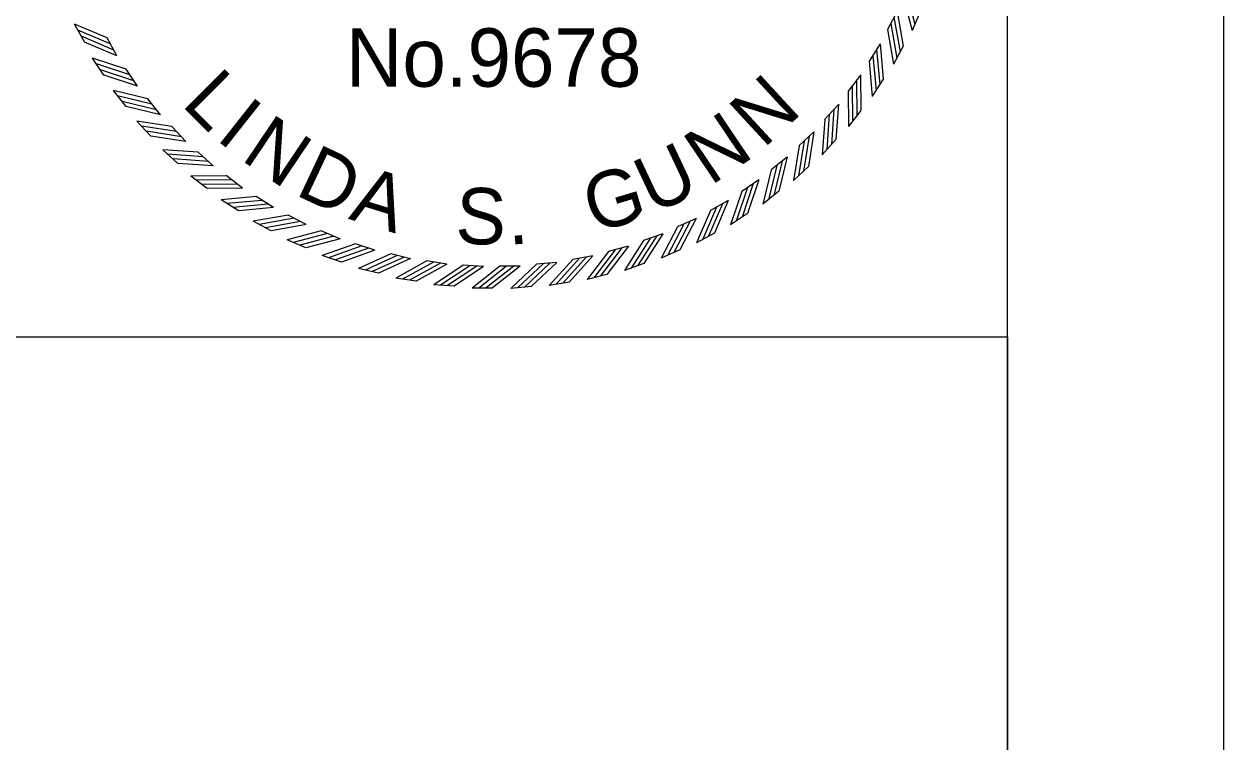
# Model space of a CAD drawing. Extents: x 0 to 1228740, y 0 to 152440.
# Drawn here: x 30.801 to 34, y 16.325 to 18.239 of the extents above; entities that cross this region are included whole.
import ezdxf

# ---------------------------------------------------------------- set-up
doc = ezdxf.new("R2010")
doc.units = 0
for name, color, linetype in [('R_Border', 7, 'Continuous'), ('R_No Plot', 7, 'Continuous'), ('STAMP', 7, 'Continuous')]:
    doc.layers.add(name, color=color, linetype=linetype)

msp = doc.modelspace()

# ---------------------------------------------------------------- linework, layer by layer
at = {"layer": 'R_Border'}
msp.add_line((33.4231, 0.5768), (33.4231, 21.4232), dxfattribs=at)
msp.add_lwpolyline([(33.9999, 22), (0, 22), (0, 0), (33.9999, 0)], close=True, dxfattribs=at)
at = {"layer": 'R_No Plot'}
for points in [[(30.6665, 20.1432), (30.6665, 17.4052), (33.4231, 17.4052)], [(33.4231, 17.4052), (33.4231, 10.8708)]]:
    msp.add_lwpolyline(points, dxfattribs=at)
at = {"layer": 'STAMP'}
for p, q in [((33.1283, 18.273), (33.1027, 18.2248)), ((33.1902, 18.2722), (33.1688, 18.2222)), ((30.9621, 18.1915), (30.9357, 18.2391)), ((31.0487, 18.1545), (31.0223, 18.2022)), ((33.083, 18.1863), (33.0536, 18.1403)), ((33.1447, 18.1803), (33.1192, 18.1323)), ((31.0141, 18.1031), (30.9839, 18.1484)), ((31.1035, 18.0734), (31.0732, 18.1188)), ((33.0308, 18.1035), (32.9977, 18.0601)), ((33.0917, 18.0925), (33.0624, 18.0467)), ((31.0733, 18.0193), (31.0395, 18.062)), ((31.1648, 17.9971), (31.1309, 18.0399)), ((32.9719, 18.0253), (32.9353, 17.9849)), ((31.1392, 17.9407), (31.102, 17.9804)), ((33.0317, 18.0093), (32.9987, 17.9661)), ((31.2322, 17.9262), (31.1949, 17.966)), ((32.9067, 17.9523), (32.8669, 17.915)), ((32.965, 17.9314), (32.9286, 17.8911)), ((31.2113, 17.8678), (31.1709, 17.9043)), ((31.3052, 17.861), (31.2648, 17.8976)), ((32.8357, 17.8849), (32.793, 17.851)), ((32.8922, 17.8593), (32.8525, 17.8221)), ((31.2892, 17.8012), (31.246, 17.8342)), ((31.3834, 17.8021), (31.34, 17.8352)), ((32.7595, 17.8236), (32.7141, 17.7933)), ((32.8136, 17.7934), (32.7709, 17.7596)), ((31.3724, 17.7411), (31.3266, 17.7705)), ((31.4661, 17.7499), (31.4202, 17.7793)), ((32.6784, 17.7688), (32.6306, 17.7424)), ((31.5529, 17.7046), (31.5047, 17.7301)), ((32.7298, 17.7342), (32.6845, 17.704)), ((31.4602, 17.6882), (31.4121, 17.7136)), ((32.593, 17.7208), (32.5433, 17.6985)), ((31.5521, 17.6427), (31.5021, 17.6641)), ((31.6432, 17.6667), (31.593, 17.6882)), ((32.504, 17.6801), (32.4526, 17.662)), ((32.6414, 17.6822), (32.5938, 17.6558)), ((31.7362, 17.6364), (31.6845, 17.6536)), ((32.4119, 17.6469), (32.3592, 17.633)), ((32.549, 17.6376), (32.4994, 17.6153)), ((31.6475, 17.6049), (31.5959, 17.6221)), ((31.8315, 17.6138), (31.7785, 17.6267)), ((31.9283, 17.5992), (31.8744, 17.6077)), ((32.0259, 17.5927), (31.9715, 17.5967)), ((32.2212, 17.6038), (32.1669, 17.5988)), ((32.3175, 17.6214), (32.2637, 17.6119)), ((32.4533, 17.6008), (32.402, 17.5827)), ((31.7456, 17.5751), (31.6928, 17.588)), ((32.1238, 17.5942), (32.0692, 17.5937)), ((32.3549, 17.572), (32.3023, 17.5582)), ((31.8459, 17.5536), (31.7922, 17.5621)), ((31.9476, 17.5404), (31.8934, 17.5444)), ((32.0501, 17.5356), (31.9957, 17.5351)), ((32.1526, 17.5393), (32.0984, 17.5343)), ((32.2544, 17.5515), (32.2008, 17.5421))]:
    msp.add_line(p, q, dxfattribs=at)
for points in [[(33.1448, 18.3132), (33.1688, 18.2222)], [(33.1521, 18.3298), (33.1761, 18.2388)], [(33.1282, 18.2731), (33.1447, 18.1804)], [(31.0223, 18.2022), (30.9357, 18.2391)], [(33.1114, 18.2408), (33.1279, 18.1481)], [(33.1199, 18.2577), (33.1364, 18.165)], [(31.0309, 18.1862), (30.9443, 18.2232)], [(31.0404, 18.1699), (30.9538, 18.2068)], [(33.1028, 18.2249), (33.1193, 18.1322)], [(31.0487, 18.1545), (30.9621, 18.1914)], [(33.0734, 18.1717), (33.0822, 18.0779)], [(33.083, 18.1863), (33.0917, 18.0926)], [(31.0732, 18.1187), (30.9839, 18.1484)], [(33.0537, 18.1404), (33.0624, 18.0466)], [(33.0636, 18.1555), (33.0723, 18.0618)], [(31.0831, 18.1036), (30.9938, 18.1332)], [(31.094, 18.0881), (31.0046, 18.1177)], [(31.1035, 18.0734), (31.0142, 18.1031)], [(33.02, 18.0898), (33.021, 17.9956)], [(33.0308, 18.1036), (33.0317, 18.0094)], [(31.1309, 18.0398), (31.0394, 18.062)], [(31.142, 18.0255), (31.0505, 18.0477)], [(32.9977, 18.0602), (32.9987, 17.966)], [(33.0089, 18.0745), (33.0098, 17.9803)], [(31.1541, 18.0109), (31.0626, 18.0331)], [(31.1649, 17.9971), (31.0734, 18.0193)], [(32.96, 18.0125), (32.9532, 17.9186)], [(32.9719, 18.0254), (32.9651, 17.9315)], [(31.1949, 17.9659), (31.1019, 17.9804)], [(32.9354, 17.9849), (32.9286, 17.891)], [(32.9477, 17.9982), (32.9408, 17.9043)], [(31.2072, 17.9526), (31.1142, 17.9671)], [(31.2204, 17.939), (31.1274, 17.9536)], [(32.9067, 17.9524), (32.8922, 17.8594)], [(31.2323, 17.9262), (31.1393, 17.9407)], [(32.867, 17.915), (32.8525, 17.822)], [(32.8803, 17.9273), (32.8658, 17.8343)], [(32.8938, 17.9405), (32.8793, 17.8475)], [(31.2648, 17.8975), (31.1709, 17.9043)], [(31.2781, 17.8852), (31.1842, 17.8921)], [(32.8358, 17.885), (32.8136, 17.7935)], [(31.2924, 17.8729), (31.1985, 17.8797)], [(31.3053, 17.861), (31.2114, 17.8678)], [(32.7931, 17.851), (32.7709, 17.7595)], [(32.8074, 17.8621), (32.7852, 17.7706)], [(32.8219, 17.8742), (32.7998, 17.7827)], [(31.3401, 17.8351), (31.2459, 17.8342)], [(31.3544, 17.824), (31.2602, 17.8231)], [(32.7595, 17.8237), (32.7298, 17.7343)], [(31.3696, 17.8129), (31.2755, 17.8119)], [(31.3835, 17.8021), (31.2893, 17.8012)], [(32.7142, 17.7933), (32.6845, 17.704)], [(32.7293, 17.8032), (32.6997, 17.7139)], [(32.7448, 17.8141), (32.7152, 17.7247)], [(31.4203, 17.7792), (31.3265, 17.7705)], [(31.4354, 17.7693), (31.3417, 17.7606)], [(31.4516, 17.7595), (31.3578, 17.7507)], [(32.663, 17.7605), (32.6261, 17.6739)], [(32.6784, 17.7688), (32.6415, 17.6823)], [(31.4662, 17.7499), (31.3725, 17.7411)], [(31.5048, 17.7301), (31.4121, 17.7136)], [(32.6307, 17.7424), (32.5938, 17.6558)], [(32.6467, 17.751), (32.6097, 17.6644)], [(31.5207, 17.7215), (31.428, 17.705)], [(31.5376, 17.713), (31.4449, 17.6965)], [(31.553, 17.7046), (31.4603, 17.6882)], [(32.5434, 17.6985), (32.4994, 17.6152)], [(32.56, 17.7058), (32.516, 17.6225)], [(32.577, 17.7139), (32.5331, 17.6306)], [(32.5931, 17.7209), (32.5491, 17.6377)], [(31.5931, 17.6881), (31.5021, 17.6641)], [(31.6097, 17.6808), (31.5187, 17.6568)], [(31.6272, 17.6738), (31.5362, 17.6497)], [(31.6433, 17.6667), (31.5522, 17.6427)], [(32.4527, 17.6619), (32.402, 17.5826)], [(32.4698, 17.6678), (32.4191, 17.5885)], [(32.4875, 17.6745), (32.4368, 17.5952)], [(32.5041, 17.6802), (32.4534, 17.6009)], [(31.6845, 17.6536), (31.5958, 17.6221)], [(31.7017, 17.6477), (31.613, 17.6162)], [(31.7197, 17.6421), (31.631, 17.6106)], [(31.7363, 17.6364), (31.6476, 17.6049)], [(32.3593, 17.633), (32.3022, 17.5581)], [(32.3769, 17.6375), (32.3198, 17.5626)], [(32.395, 17.6427), (32.338, 17.5678)], [(32.412, 17.647), (32.3549, 17.5721)], [(31.7785, 17.6267), (31.6927, 17.588)], [(31.7961, 17.6222), (31.7103, 17.5835)], [(31.8146, 17.6182), (31.7288, 17.5795)], [(31.8316, 17.6139), (31.7457, 17.5752)], [(31.8744, 17.6077), (31.7921, 17.562)], [(31.8923, 17.6047), (31.81, 17.559)], [(31.9111, 17.6022), (31.8287, 17.5565)], [(31.9283, 17.5993), (31.846, 17.5536)], [(31.9716, 17.5966), (31.8933, 17.5443)], [(31.9896, 17.5951), (31.9114, 17.5428)], [(32.1669, 17.5988), (32.0983, 17.5343)], [(32.185, 17.6003), (32.1164, 17.5358)], [(32.2038, 17.6024), (32.1352, 17.538)], [(32.2212, 17.6039), (32.1526, 17.5394)], [(32.2638, 17.6119), (32.2008, 17.542)], [(32.2817, 17.6149), (32.2186, 17.545)], [(32.3002, 17.6186), (32.2372, 17.5487)], [(32.3175, 17.6215), (32.2545, 17.5516)], [(32.0085, 17.5942), (31.9302, 17.5419)], [(32.026, 17.5927), (31.9477, 17.5404)], [(32.0693, 17.5937), (31.9956, 17.5351)], [(32.0874, 17.5937), (32.0137, 17.5351)], [(32.1063, 17.5943), (32.0326, 17.5357)], [(32.1238, 17.5943), (32.0501, 17.5357)]]:
    msp.add_lwpolyline(points, dxfattribs=at)

# ---------------------------------------------------------------- texts
msp.add_text('No.9678', height=0.15578, dxfattribs=at).set_placement((31.6592, 18.0722))
for s, rotation, p in [('L', 315.1295, (31.218, 18.0244)), ('N', 42.6817, (32.7717, 17.9056)), ('I', 321.696, (31.3094, 17.9334)), ('N', 326.0736, (31.3759, 17.8788)), ('N', 33.9264, (32.6309, 17.8069)), ('U', 25.1712, (32.4767, 17.7308)), ('D', 334.8288, (31.5203, 17.7856)), ('G', 16.7808, (32.3198, 17.6807)), ('A', 342.8544, (31.6638, 17.7204)), ('S', 357.8112, (31.9495, 17.6547)), ('.', 5.1072, (32.0928, 17.6502))]:
    msp.add_text(s, height=0.1503, rotation=rotation, dxfattribs=at).set_placement(p)

doc.saveas('drawing.dxf')
